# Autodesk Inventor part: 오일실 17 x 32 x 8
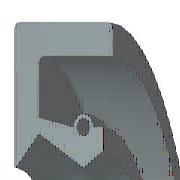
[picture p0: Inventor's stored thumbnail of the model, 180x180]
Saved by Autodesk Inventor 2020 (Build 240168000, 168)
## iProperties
Created: 2012-02
Part Number: 오일실 17 x 32 x 8
Material: 고무
Description: 오일-실
Document SubType Name: Modeling
Standard: KS B 2804
Designer: mduedu
Standards Organization: KS
Language: ko-KR
Size Designation: D - 17 32 8
Categories: <MemberInstance><Categories><Category DisplayName="샤프트 부품" InternalName="7f7aeb1f-a693-4053-b835-cee3144e0d98" Mnemonic="SHFT"><Category DisplayName="실링" Intern
Density: 0.93 g/cm^3
Appearance: 고무 - 검은색 - 버전 1.1
IsCustomPart: 1
Author: mduedu
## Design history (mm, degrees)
revolve "본체" stored, may be unused: angle "d17" = 90 deg
revolve "스프링1" stored, may be unused: angle "d18" = 90 deg
body "Solid1"
sketch "스케치1"
  geometry: L1 (0, 16)-(8, 16); L2 (8, 14.25)-(1.75, 14.25); L3 (1.75, 10.25)-(4.9, 8.5); L4 (4.9, 8.5)-(0, 8.5); L5 (0, 0)-(9.586, 0) reference; L6 (4.9, 8.5)-(6.3, 9.375); L7 (0, 18)-(0, -3) reference; L8 (-1.941, 0)-(11.507, 0) reference; L9 (4.2, 10.6)-(1.75, 11.21); L10 (1.75, 11.21)-(1.75, 14.25); L11 (0, 16)-(0, 8.588); L12 (4.9, 8.5)-(0, 8.5); L13 (1.75, 10.25)-(0.152, 8.528); L14 (8, 16)-(8, 14.25); L15 (5.6, 10.6)-(6.3, 10.6); L16 (6.3, 10.6)-(6.3, 9.375); C1 r 0.455 at (4.9, 10.6); A1 r 0.7 centre (4.9, 10.6) between (5.6, 10.6) and (4.2, 10.6); A2 r 0.088 centre (0.088, 8.588) between (0, 8.588) and (0.152, 8.528); 1 further point
  constraints: 28 end point, 5 horizontal alignment, 5 point on line, 4 point on circle, 4 vertical alignment, 3 centre point, 3 tangent, 2 collinear, 2 horizontal, 2 perpendicular, 1 coincident, 1 parallel
  dimensions: "d0" = 32 diameter of L1 L5 (= SD2); "d1" = 1.75 distance of L1.end L2.start (= SD); "d2" = 0.91 diameter of C1 (= SPDI); "d3" = 1.4 diameter of A1 (= SPDA); "d4" = 17 diameter of L3.end L5 (= NND); "d5" = 20.5 diameter of L3.start L5 (= TKDM); "d7" = 22.42 diameter of L9.end L5 (= TKDM + 0.24 x SWDT); "d8" = 1.75 distance between parallel lines of L11 L10 (= SD); "d9" = 4.9 distance from line of L11 C1.centre (= SPDST); "d10" = 21.2 diameter of C1.centre L5 (= HLDM); "d11" = 0.0875 radius of A2 (= 0.25 x LAB); "d12" = 6.3 distance between parallel lines of L11 L16 (= SDI); "d13" = 18.75 diameter of L6.end L5 (= ABDM); "d14" = 8 distance from line of L11 L1.end (= SWDT)
fillet "모깎기1" dims "d6" = 0.3 (= RR)
other parameters: "SD2" = 32 [user parameter; used in 1 equation term], "SWDT" = 8 [user parameter; used in 2 equation terms], "RR" = 0.3 [user parameter; used in 1 equation term], "SD" = 1.75 [user parameter; used in 2 equation terms], "NND" = 17 [user parameter; used in 1 equation term], "SPDA" = 1.4 [user parameter; used in 1 equation term], "SPDI" = 0.91 [user parameter; used in 1 equation term], "TKDM" = 20.5 [user parameter; used in 2 equation terms], "HLDM" = 21.2 [user parameter; used in 1 equation term], "ABDM" = 18.75 [user parameter; used in 1 equation term], "SDI" = 6.3 [user parameter; used in 1 equation term], "SPDST" = 4.9 [user parameter; used in 1 equation term], "LAB" = 0.35 [user parameter; used in 1 equation term], "d15" = 0, "d16" = 0, "d19" = 0
